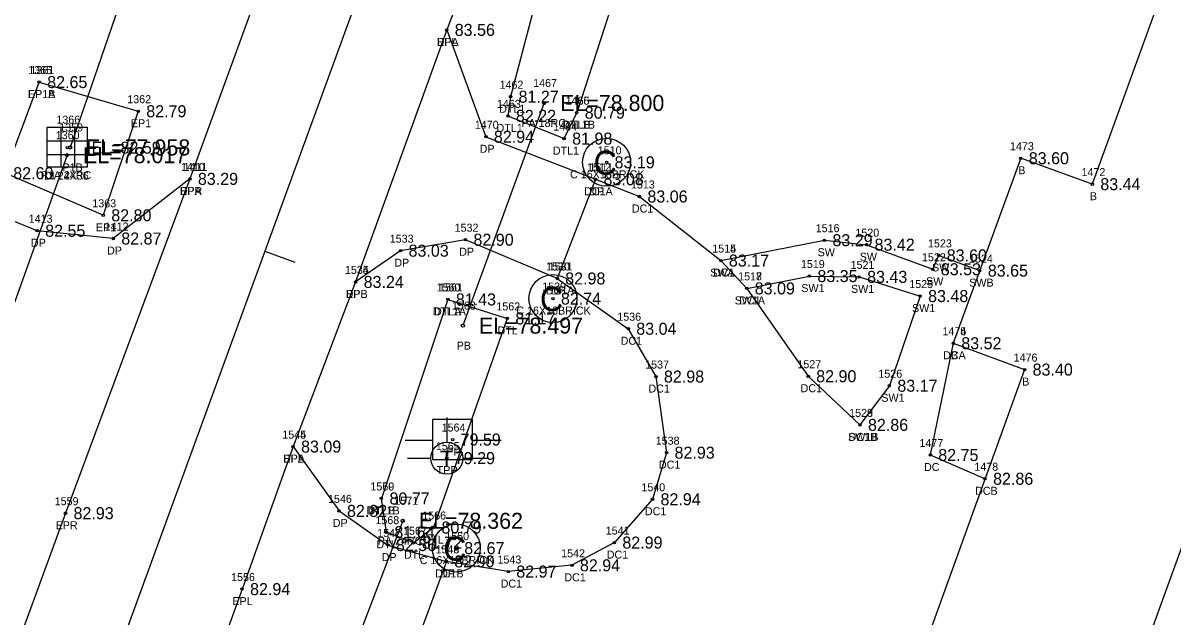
# Model space of a CAD drawing. Extents: x 2139392 to 2143384, y 505395 to 510520.
# Drawn here: x 2141170.6 to 2141314.3, y 509673.1 to 509747.3 of the extents above; entities that cross this region are included whole.
import ezdxf

# ---------------------------------------------------------------- set-up
doc = ezdxf.new("R2010")
doc.units = 0
for name, color, linetype in [('RD_EX_Bldg', 7, 'Continuous'), ('RD_EX_Bldg_txCode', 7, 'Continuous'), ('RD_EX_BldgApp', 7, 'Continuous'), ('RD_EX_BldgApp_txCode', 7, 'Continuous'), ('RD_EX_Conc', 7, 'Continuous'), ('RD_EX_Conc_txCode', 7, 'Continuous'), ('RD_EX_DR_Inlet', 7, 'Continuous'), ('RD_EX_DR_Inlet_txCode', 7, 'Continuous'), ('RD_EX_DR_Pipe', 7, 'Continuous'), ('RD_EX_DR_Pipe_txCode', 7, 'Continuous'), ('RD_EX_Driveway', 7, 'Continuous'), ('RD_EX_Driveway_txCode', 7, 'Continuous'), ('RD_EX_H2O', 7, 'Continuous'), ('RD_EX_H2O_txCode', 7, 'Continuous'), ('RD_EX_Road', 7, 'Continuous'), ('RD_EX_Road_txCode', 7, 'Continuous'), ('RD_EX_TX_Bldg_ELEV', 7, 'Continuous'), ('RD_EX_TX_BldgApp_ELEV', 7, 'Continuous'), ('RD_EX_TX_Conc_ELEV', 7, 'Continuous'), ('RD_EX_TX_DR_Inlet_ELEV', 7, 'Continuous'), ('RD_EX_TX_Driveway_ELEV', 7, 'Continuous'), ('RD_EX_TX_H2O_ELEV', 7, 'Continuous'), ('RD_EX_TX_Road_ELEV', 7, 'Continuous'), ('RD_EX_TX_UT_ELEV', 7, 'Continuous'), ('RD_EX_UT', 7, 'Continuous'), ('RD_EX_UT_txCode', 7, 'Continuous'), ('RD_HC_Cl', 7, 'Continuous'), ('RD_HC_Data_Tic', 7, 'Continuous'), ('RD_HC_Survey_ELEV', 7, 'Continuous'), ('RD_SMD_Locator', 7, 'Continuous'), ('RD_TX_Pipe_ElevEX', 7, 'Continuous')]:
    doc.layers.add(name, color=color, linetype=linetype)

msp = doc.modelspace()

# ---------------------------------------------------------------- linework, layer by layer
at = {"layer": 'RD_EX_Bldg'}
msp.add_lwpolyline([(2141313.23, 509752.05), (2141304.22, 509727.14), (2141295.28, 509730.38), (2141286.85, 509707.27), (2141295.76, 509703.98), (2141281.84, 509665.49), (2141306.21, 509656.42), (2141337.67, 509743.19), (2141313.23, 509752.05)], dxfattribs=at)
at = {"layer": 'RD_EX_BldgApp'}
for centre in [(2141243.53, 509729.87), (2141236.83, 509712.85), (2141224.75, 509681.68)]:
    msp.add_circle(centre, 3, dxfattribs=at)
at = {"layer": 'RD_EX_Conc'}
for points in [[(2141242.15, 509727.75), (2141247.63, 509725.6), (2141257.81, 509717.6), (2141261.04, 509714.12), (2141268.72, 509703.15), (2141275.19, 509697.07)], [(2141257.81, 509717.6), (2141270.75, 509720.14), (2141276.01, 509719.58), (2141284.29, 509716.51), (2141285.03, 509718.24), (2141290.16, 509716.34)], [(2141237.36, 509715.36), (2141246.24, 509709.08), (2141249.7, 509703.11), (2141251.02, 509693.6), (2141249.27, 509687.78), (2141244.5, 509682.37), (2141239.2, 509679.53), (2141231.25, 509678.75), (2141223.51, 509680.02)], [(2141261.04, 509714.12), (2141268.87, 509715.66), (2141275.08, 509715.56), (2141282.7, 509713.16), (2141278.86, 509701.96), (2141275.19, 509697.07)], [(2141286.85, 509707.27), (2141283.97, 509693.31), (2141290.82, 509690.34)]]:
    msp.add_lwpolyline(points, dxfattribs=at)
at = {"layer": 'RD_EX_DR_Inlet'}
for p, q in [((2141175.35, 509734.26), (2141175.35, 509729.26)), ((2141177.05, 509734.26), (2141177.05, 509729.26)), ((2141173.65, 509732.56), (2141178.65, 509732.56)), ((2141173.65, 509730.86), (2141178.65, 509730.86))]:
    msp.add_line(p, q, dxfattribs=at)
msp.add_lwpolyline([(2141173.65, 509729.26), (2141173.65, 509734.26), (2141178.65, 509734.26), (2141178.65, 509729.26)], close=True, dxfattribs=at)
at = {"layer": 'RD_EX_DR_Pipe'}
for p, q in [((2141192.1, 509776.83), (2141176.5, 509731.73)), ((2141235.73, 509737.28), (2141225.58, 509709.47)), ((2141176.12, 509730.76), (2141125.75, 509590.72)), ((2141218.07, 509685.09), (2141209.05, 509661.44))]:
    msp.add_line(p, q, dxfattribs=at)
at = {"layer": 'RD_EX_Driveway'}
for points in [[(2141223.56, 509746.41), (2141228.45, 509733.06), (2141242.15, 509727.75), (2141237.36, 509715.36), (2141225.9, 509720.2), (2141217.79, 509718.83), (2141212.18, 509714.93)], [(2141191.47, 509727.8), (2141181.9, 509720.35), (2141172.39, 509721.32), (2141164.15, 509724.67), (2141156.72, 509705.7), (2141152.41, 509694.43), (2141146.18, 509677.35), (2141143.5, 509670.11), (2141126.23, 509619.16), (2141121.57, 509618.23), (2141114.74, 509598.13), (2141140.09, 509588.3)], [(2141204.36, 509694.36), (2141210.1, 509686.33), (2141216.21, 509682.06), (2141223.51, 509680.02), (2141217.48, 509663.63), (2141210.53, 509667.64), (2141203.7, 509668.91), (2141193.66, 509664.6)]]:
    msp.add_lwpolyline(points, dxfattribs=at)
at = {"layer": 'RD_EX_H2O'}
msp.add_line((2141223.7, 509712.74), (2141215.4, 509687.88), dxfattribs=at)
for points in [[(2141247.26, 509773.42), (2141240.68, 509772.91), (2141231.53, 509738.06), (2141231.2, 509735.67), (2141238.23, 509732.83), (2141239.8, 509736.07)], [(2141247.26, 509773.42), (2141250.66, 509769.48), (2141239.8, 509736.07)], [(2141223.7, 509712.74), (2141231.13, 509710.37), (2141221.9, 509684.25), (2141219.47, 509682.35), (2141216.02, 509683.67), (2141215.4, 509687.88)]]:
    msp.add_lwpolyline(points, dxfattribs=at)
at = {"layer": 'RD_EX_Road'}
for points in [[(2141389.23, 510293.58), (2141374.66, 510243.58), (2141359.1, 510192.72), (2141341.17, 510140.58), (2141322.74, 510087.97), (2141303.61, 510035.12), (2141287.18, 509990.16), (2141276.99, 509962.02), (2141248.91, 509884.35), (2141213.37, 509787.47), (2141207.76, 509772.94), (2141199.35, 509749.36), (2141191.47, 509727.8), (2141175.93, 509686.04), (2141140.09, 509588.3), (2141106.08, 509494.11), (2141096.82, 509469.24), (2141063.82, 509378.98), (2141052.52, 509348.48), (2141043.48, 509323.88)], [(2141412.62, 510288.46), (2141398.29, 510238.16), (2141381.65, 510185.39), (2141379.05, 510176.51), (2141367.08, 510141.57), (2141363.58, 510131.95), (2141345.23, 510080.36), (2141326.05, 510027.03), (2141308.64, 509979.4), (2141271.24, 509876.37), (2141240, 509789.51), (2141233.78, 509773.43), (2141223.56, 509746.41), (2141212.18, 509714.93), (2141204.36, 509694.36), (2141197.99, 509676.56), (2141193.66, 509664.6), (2141161.61, 509577.24), (2141123.75, 509473.61), (2141115.5, 509450.65), (2141102.09, 509414.61), (2141086.27, 509371.27), (2141050.42, 509272.83)], [(2141172.64, 509739.89), (2141185.02, 509736.25), (2141180.65, 509723.25), (2141168.4, 509728.51), (2141172.64, 509739.89)]]:
    msp.add_lwpolyline(points, dxfattribs=at)
at = {"layer": 'RD_EX_UT'}
for p, q in [((2141226.78, 509697.75), (2141221.78, 509697.75)), ((2141221.78, 509697.75), (2141221.78, 509692.75)), ((2141223.57, 509697.99), (2141223.57, 509694.92)), ((2141226.78, 509692.75), (2141226.78, 509697.75)), ((2141218.35, 509695.18), (2141221.82, 509695.18)), ((2141226.71, 509695.18), (2141230.35, 509695.18)), ((2141218.64, 509692.93), (2141221.57, 509692.93)), ((2141225.57, 509692.93), (2141228.64, 509692.93)), ((2141221.78, 509692.75), (2141226.78, 509692.75))]:
    msp.add_line(p, q, dxfattribs=at)
msp.add_circle((2141223.57, 509692.92), 2, dxfattribs=at)
at = {"layer": 'RD_HC_Cl'}
msp.add_line((2141333.53, 510081.69), (2140670.51, 508268.37), dxfattribs=at)
at = {"layer": 'RD_HC_Data_Tic'}
msp.add_line((2141200.83, 509718.77), (2141204.59, 509717.4), dxfattribs=at)
at = {"layer": 'RD_SMD_Locator'}
for centre, radius in [((2141223.56, 509746.41), 0.15), ((2141223.56, 509746.41), 0.15), ((2141172.64, 509739.89), 0.15), ((2141172.64, 509739.89), 0.15), ((2141231.53, 509738.06), 0.15), ((2141235.73, 509737.28), 0.2), ((2141185.02, 509736.25), 0.15), ((2141239.8, 509736.07), 0.15), ((2141239.8, 509736.07), 0.15), ((2141231.2, 509735.67), 0.15), ((2141228.45, 509733.06), 0.15), ((2141176.18, 509731.7), 0.15), ((2141176.5, 509731.73), 0.2), ((2141238.23, 509732.83), 0.15), ((2141176.12, 509730.76), 0.2), ((2141295.28, 509730.38), 0.15), ((2141243.53, 509729.87), 0.15), ((2141191.47, 509727.8), 0.15), ((2141191.47, 509727.8), 0.15), ((2141242.15, 509727.75), 0.15), ((2141242.15, 509727.75), 0.15), ((2141304.22, 509727.14), 0.15), ((2141247.63, 509725.6), 0.15), ((2141180.65, 509723.25), 0.15), ((2141172.39, 509721.32), 0.15), ((2141181.9, 509720.35), 0.15), ((2141225.9, 509720.2), 0.15), ((2141270.75, 509720.14), 0.15), ((2141217.79, 509718.83), 0.15), ((2141276.01, 509719.58), 0.15), ((2141257.81, 509717.6), 0.15), ((2141257.81, 509717.6), 0.15), ((2141285.03, 509718.24), 0.15), ((2141268.87, 509715.66), 0.15), ((2141284.29, 509716.51), 0.15), ((2141290.16, 509716.34), 0.15), ((2141212.18, 509714.93), 0.15), ((2141212.18, 509714.93), 0.15), ((2141237.36, 509715.36), 0.15), ((2141237.36, 509715.36), 0.15), ((2141275.08, 509715.56), 0.15), ((2141236.83, 509712.85), 0.15), ((2141261.04, 509714.12), 0.15), ((2141261.04, 509714.12), 0.15), ((2141282.7, 509713.16), 0.15), ((2141223.7, 509712.74), 0.15), ((2141223.7, 509712.74), 0.15), ((2141231.13, 509710.37), 0.15), ((2141225.58, 509709.47), 0.2), ((2141246.24, 509709.08), 0.15), ((2141286.85, 509707.27), 0.15), ((2141286.85, 509707.27), 0.15), ((2141249.7, 509703.11), 0.15), ((2141268.72, 509703.15), 0.15), ((2141295.76, 509703.98), 0.15), ((2141278.86, 509701.96), 0.15), ((2141275.19, 509697.07), 0.15), ((2141275.19, 509697.07), 0.15), ((2141204.36, 509694.36), 0.15), ((2141204.36, 509694.36), 0.15), ((2141224.29, 509695.24), 0.15), ((2141223.57, 509692.92), 0.15), ((2141251.02, 509693.6), 0.15), ((2141283.97, 509693.31), 0.15), ((2141290.82, 509690.34), 0.15), ((2141215.4, 509687.88), 0.15), ((2141215.4, 509687.88), 0.15), ((2141249.27, 509687.78), 0.15), ((2141175.93, 509686.04), 0.15), ((2141210.1, 509686.33), 0.15), ((2141218.07, 509685.09), 0.2), ((2141221.9, 509684.25), 0.15), ((2141216.02, 509683.67), 0.15), ((2141216.21, 509682.06), 0.15), ((2141219.47, 509682.35), 0.15), ((2141224.75, 509681.68), 0.15), ((2141244.5, 509682.37), 0.15), ((2141223.51, 509680.02), 0.15), ((2141223.51, 509680.02), 0.15), ((2141231.25, 509678.75), 0.15), ((2141239.2, 509679.53), 0.15), ((2141197.99, 509676.56), 0.15)]:
    msp.add_circle(centre, radius, dxfattribs=at)

# ---------------------------------------------------------------- texts
at = {"layer": 'RD_EX_Bldg_txCode'}
for s, p in [('1473', (2141293.93, 509731.38)), ('B', (2141294.97, 509728.38)), ('1472', (2141302.87, 509728.14)), ('B', (2141303.91, 509725.14)), ('1474', (2141285.5, 509708.27)), ('B', (2141286.54, 509705.27)), ('1476', (2141294.39, 509704.98)), ('B', (2141295.45, 509701.98))]:
    msp.add_text(s, height=1, dxfattribs=at).set_placement(p)
at = {"layer": 'RD_EX_BldgApp'}
for p in [(2141241.9, 509728.31), (2141235.2, 509711.29), (2141223.12, 509680.12)]:
    msp.add_text('C', height=3, dxfattribs=at).set_placement(p)
at = {"layer": 'RD_EX_BldgApp_txCode'}
for s, p in [('1510', (2141242.43, 509730.87)), ('C 16X16BRICK', (2141238.97, 509727.87)), ('1539', (2141235.49, 509713.85)), ('C 16X16BRICK', (2141232.26, 509710.85)), ('1550', (2141223.37, 509682.68)), ('C 16X16BRICK', (2141220.19, 509679.68))]:
    msp.add_text(s, height=1, dxfattribs=at).set_placement(p)
at = {"layer": 'RD_EX_Conc_txCode'}
for s, p in [('1512', (2141241.09, 509728.75)), ('1513', (2141246.57, 509726.6)), ('DC1A', (2141240.72, 509725.75)), ('DC1', (2141246.69, 509723.6)), ('1516', (2141269.66, 509721.14)), ('1520', (2141274.62, 509720.58)), ('1523', (2141283.69, 509719.24)), ('1514', (2141256.74, 509718.6)), ('1515', (2141256.74, 509718.6)), ('SW', (2141269.9, 509718.14)), ('1531', (2141236.3, 509716.36)), ('1519', (2141267.81, 509716.66)), ('1521', (2141274.02, 509716.56)), ('SW', (2141275.16, 509717.58)), ('1522', (2141282.94, 509717.51)), ('SW', (2141284.19, 509716.24)), ('1524', (2141288.81, 509717.34)), ('SWA', (2141256.48, 509715.6)), ('DC1', (2141256.86, 509715.6)), ('1518', (2141259.97, 509715.12)), ('1517', (2141259.97, 509715.12)), ('DC1A', (2141235.93, 509713.36)), ('SW1', (2141267.86, 509713.66)), ('SW1', (2141274.07, 509713.56)), ('1525', (2141281.35, 509714.16)), ('SW', (2141283.45, 509714.51)), ('SWB', (2141288.84, 509714.34)), ('SW1A', (2141259.54, 509712.12)), ('DC1', (2141260.09, 509712.12)), ('SW1', (2141281.69, 509711.16)), ('1536', (2141244.87, 509710.08)), ('1475', (2141285.5, 509708.27)), ('DC1', (2141245.29, 509707.08)), ('DCA', (2141285.58, 509705.27)), ('1537', (2141248.35, 509704.11)), ('1527', (2141267.37, 509704.15)), ('1526', (2141277.49, 509702.96)), ('DC1', (2141248.76, 509701.11)), ('DC1', (2141267.77, 509701.15)), ('SW1', (2141277.86, 509699.96)), ('1528', (2141273.84, 509698.07)), ('1529', (2141273.84, 509698.07)), ('SW1B', (2141273.71, 509695.07)), ('DC1B', (2141273.77, 509695.07)), ('1538', (2141249.67, 509694.6)), ('1477', (2141282.62, 509694.31)), ('DC1', (2141250.07, 509691.6)), ('DC', (2141283.19, 509691.31)), ('1478', (2141289.48, 509691.34)), ('1540', (2141247.88, 509688.78)), ('DCB', (2141289.57, 509688.34)), ('DC1', (2141248.32, 509685.78)), ('1541', (2141243.43, 509683.37)), ('1549', (2141222.16, 509681.02)), ('1542', (2141237.86, 509680.53)), ('DC1', (2141243.55, 509680.37)), ('1543', (2141229.9, 509679.75)), ('DC1B', (2141222.09, 509678.02)), ('DC1', (2141238.26, 509677.53)), ('DC1', (2141230.3, 509676.75))]:
    msp.add_text(s, height=1, dxfattribs=at).set_placement(p)
at = {"layer": 'RD_EX_DR_Inlet_txCode'}
for s, p in [('1366', (2141174.79, 509734.7)), ('DI 24X36', (2141173.25, 509727.7))]:
    msp.add_text(s, height=1, dxfattribs=at).set_placement(p)
at = {"layer": 'RD_EX_DR_Pipe_txCode'}
for s, p in [('1467', (2141234.36, 509739.28)), ('1359', (2141175.15, 509733.73)), ('PA 18RC', (2141232.89, 509734.28)), ('1360', (2141174.71, 509732.76)), ('P1A 24RC', (2141172.83, 509727.76)), ('P1B', (2141175.55, 509728.73)), ('1563', (2141224.21, 509711.47)), ('PB', (2141224.8, 509706.47)), ('1571', (2141217.01, 509687.09)), ('PA 24RC', (2141214.94, 509682.09))]:
    msp.add_text(s, height=1, dxfattribs=at).set_placement(p)
at = {"layer": 'RD_EX_Driveway_txCode'}
for s, p in [('DPA', (2141222.3, 509744.41)), ('1470', (2141227.07, 509734.06)), ('DP', (2141227.67, 509731.06)), ('1411', (2141190.69, 509728.8)), ('1511', (2141241.37, 509728.75)), ('DPA', (2141190.2, 509725.8)), ('DP', (2141241.37, 509725.75)), ('1413', (2141171.33, 509722.32)), ('1412', (2141180.83, 509721.35)), ('1532', (2141224.55, 509721.2)), ('DP', (2141171.61, 509719.32)), ('1533', (2141216.44, 509719.83)), ('DP', (2141181.12, 509718.35)), ('DP', (2141225.12, 509718.2)), ('DP', (2141217.01, 509716.83)), ('1530', (2141235.97, 509716.36)), ('1534', (2141210.84, 509715.93)), ('DP', (2141236.58, 509713.36)), ('DPB', (2141210.93, 509712.93)), ('1545', (2141203.02, 509695.36)), ('DPA', (2141203.1, 509692.36)), ('1546', (2141208.73, 509687.33)), ('DP', (2141209.32, 509684.33)), ('1547', (2141214.87, 509683.06)), ('1548', (2141222.16, 509681.02)), ('DP', (2141215.43, 509680.06)), ('DP', (2141222.73, 509678.02))]:
    msp.add_text(s, height=1, dxfattribs=at).set_placement(p)
at = {"layer": 'RD_EX_H2O_txCode'}
for s, p in [('1462', (2141230.16, 509739.06)), ('1463', (2141229.83, 509736.67)), ('1466', (2141238.41, 509737.07)), ('1465', (2141238.43, 509737.07)), ('DTL1', (2141230.12, 509736.06)), ('DTL1', (2141229.79, 509733.67)), ('1464', (2141236.86, 509733.83)), ('DTL1B', (2141237.92, 509734.07)), ('DTLB', (2141238.09, 509734.07)), ('DTL1', (2141236.82, 509730.83)), ('1560', (2141222.29, 509713.74)), ('1561', (2141222.61, 509713.74)), ('DTL1A', (2141221.8, 509710.74)), ('DTLA', (2141221.97, 509710.74)), ('1562', (2141229.76, 509711.37)), ('DTL', (2141229.89, 509708.37)), ('1570', (2141214.02, 509688.88)), ('1569', (2141214.03, 509688.88)), ('DTL1B', (2141213.52, 509685.88)), ('DTLB', (2141213.68, 509685.88)), ('1568', (2141214.65, 509684.67)), ('1566', (2141220.5, 509685.25)), ('1567', (2141218.1, 509683.35)), ('DTL', (2141220.65, 509682.25)), ('DTL', (2141214.78, 509681.67)), ('DTL', (2141218.22, 509680.35))]:
    msp.add_text(s, height=1, dxfattribs=at).set_placement(p)
at = {"layer": 'RD_EX_Road_txCode'}
for s, p in [('EPL', (2141222.36, 509744.41)), ('1365', (2141171.27, 509740.89)), ('1361', (2141171.55, 509740.89)), ('EP1A', (2141171.23, 509737.89)), ('EP1B', (2141171.24, 509737.89)), ('1362', (2141183.65, 509737.25)), ('EP1', (2141184.1, 509734.25)), ('1410', (2141190.37, 509728.8)), ('EPR', (2141190.24, 509725.8)), ('1363', (2141179.28, 509724.25)), ('EP1', (2141179.73, 509721.25)), ('1535', (2141210.84, 509715.93)), ('EPL', (2141210.98, 509712.93)), ('1544', (2141203.02, 509695.36)), ('EPL', (2141203.16, 509692.36)), ('1559', (2141174.58, 509687.04)), ('EPR', (2141174.7, 509684.04)), ('1556', (2141196.62, 509677.56)), ('EPL', (2141196.78, 509674.56))]:
    msp.add_text(s, height=1, dxfattribs=at).set_placement(p)
at = {"layer": 'RD_EX_TX_Bldg_ELEV'}
for s, p in [('83.60', (2141296.28, 509729.63)), ('83.44', (2141305.22, 509726.39)), ('83.52', (2141287.85, 509706.52)), ('83.40', (2141296.76, 509703.23))]:
    msp.add_text(s, height=1.5, dxfattribs=at).set_placement(p)
at = {"layer": 'RD_EX_TX_BldgApp_ELEV'}
for s, p in [('83.19', (2141244.53, 509729.12)), ('82.74', (2141237.83, 509712.1)), ('82.67', (2141225.75, 509680.93))]:
    msp.add_text(s, height=1.5, dxfattribs=at).set_placement(p)
at = {"layer": 'RD_EX_TX_Conc_ELEV'}
for s, p in [('83.08', (2141243.15, 509727)), ('83.06', (2141248.63, 509724.85)), ('83.29', (2141271.75, 509719.39)), ('83.42', (2141277.01, 509718.83)), ('83.60', (2141286.03, 509717.49)), ('83.17', (2141258.81, 509716.85)), ('83.17', (2141258.81, 509716.85)), ('83.53', (2141285.29, 509715.76)), ('82.98', (2141238.36, 509714.61)), ('83.35', (2141269.87, 509714.91)), ('83.43', (2141276.08, 509714.81)), ('83.65', (2141291.16, 509715.59)), ('83.09', (2141262.04, 509713.37)), ('83.09', (2141262.04, 509713.37)), ('83.48', (2141283.7, 509712.41)), ('83.04', (2141247.24, 509708.33)), ('83.52', (2141287.85, 509706.52)), ('82.98', (2141250.7, 509702.36)), ('82.90', (2141269.72, 509702.4)), ('83.17', (2141279.86, 509701.21)), ('82.86', (2141276.19, 509696.32)), ('82.86', (2141276.19, 509696.32)), ('82.93', (2141252.02, 509692.85)), ('82.75', (2141284.97, 509692.56)), ('82.86', (2141291.82, 509689.59)), ('82.94', (2141250.27, 509687.03)), ('82.99', (2141245.5, 509681.62)), ('82.90', (2141224.51, 509679.27)), ('82.94', (2141240.2, 509678.78)), ('82.97', (2141232.25, 509678))]:
    msp.add_text(s, height=1.5, dxfattribs=at).set_placement(p)
at = {"layer": 'RD_EX_TX_DR_Inlet_ELEV'}
msp.add_text('EL=82.59', height=1.5, dxfattribs=at).set_placement((2141179.18, 509730.95))
at = {"layer": 'RD_EX_TX_Driveway_ELEV'}
for s, p in [('83.56', (2141224.56, 509745.66)), ('82.94', (2141229.45, 509732.31)), ('83.29', (2141192.47, 509727.05)), ('83.08', (2141243.15, 509727)), ('82.55', (2141173.39, 509720.57)), ('82.87', (2141182.9, 509719.6)), ('82.90', (2141226.9, 509719.45)), ('83.03', (2141218.79, 509718.08)), ('82.98', (2141238.36, 509714.61)), ('83.24', (2141213.18, 509714.18)), ('83.09', (2141205.36, 509693.61)), ('82.82', (2141211.1, 509685.58)), ('82.56', (2141217.21, 509681.31)), ('82.90', (2141224.51, 509679.27))]:
    msp.add_text(s, height=1.5, dxfattribs=at).set_placement(p)
at = {"layer": 'RD_EX_TX_H2O_ELEV'}
for s, p in [('81.27', (2141232.53, 509737.31)), ('82.22', (2141232.2, 509734.92)), ('80.79', (2141240.8, 509735.32)), ('80.79', (2141240.8, 509735.32)), ('81.98', (2141239.23, 509732.08)), ('81.43', (2141224.7, 509711.99)), ('81.43', (2141224.7, 509711.99)), ('81.17', (2141232.13, 509709.62)), ('80.77', (2141216.4, 509687.13)), ('80.77', (2141216.4, 509687.13)), ('81.64', (2141217.02, 509682.92)), ('80.79', (2141222.9, 509683.5)), ('81.72', (2141220.47, 509681.6))]:
    msp.add_text(s, height=1.5, dxfattribs=at).set_placement(p)
at = {"layer": 'RD_EX_TX_Road_ELEV'}
for s, p in [('83.56', (2141224.56, 509745.66)), ('82.65', (2141173.64, 509739.14)), ('82.65', (2141173.64, 509739.14)), ('82.79', (2141186.02, 509735.5)), ('82.60', (2141169.4, 509727.76)), ('83.29', (2141192.47, 509727.05)), ('82.80', (2141181.65, 509722.5)), ('83.24', (2141213.18, 509714.18)), ('83.09', (2141205.36, 509693.61)), ('82.93', (2141176.93, 509685.29)), ('82.94', (2141198.99, 509675.81))]:
    msp.add_text(s, height=1.5, dxfattribs=at).set_placement(p)
at = {"layer": 'RD_EX_TX_UT_ELEV'}
msp.add_text('79.29', height=1.5, dxfattribs=at).set_placement((2141224.57, 509692.17))
at = {"layer": 'RD_EX_UT'}
msp.add_text('T', height=2, dxfattribs=at).set_placement((2141222.72, 509691.87))
at = {"layer": 'RD_EX_UT_txCode'}
for s, p in [('1564', (2141222.92, 509696.24)), ('1565', (2141222.2, 509693.92)), ('PP', (2141223.51, 509693.24)), ('TPP', (2141222.31, 509690.92))]:
    msp.add_text(s, height=1, dxfattribs=at).set_placement(p)
at = {"layer": 'RD_HC_Survey_ELEV'}
msp.add_text('79.59', height=1.5, dxfattribs=at).set_placement((2141225.29, 509694.49))
at = {"layer": 'RD_TX_Pipe_ElevEX'}
for s, p in [('EL=78.800', (2141237.73, 509736.28)), ('EL=78.017', (2141178.12, 509729.76)), ('EL=77.958', (2141178.5, 509730.73)), ('EL=78.497', (2141227.58, 509708.47)), ('EL=78.362', (2141220.07, 509684.09))]:
    msp.add_text(s, height=2, dxfattribs=at).set_placement(p)

doc.saveas('drawing.dxf')
